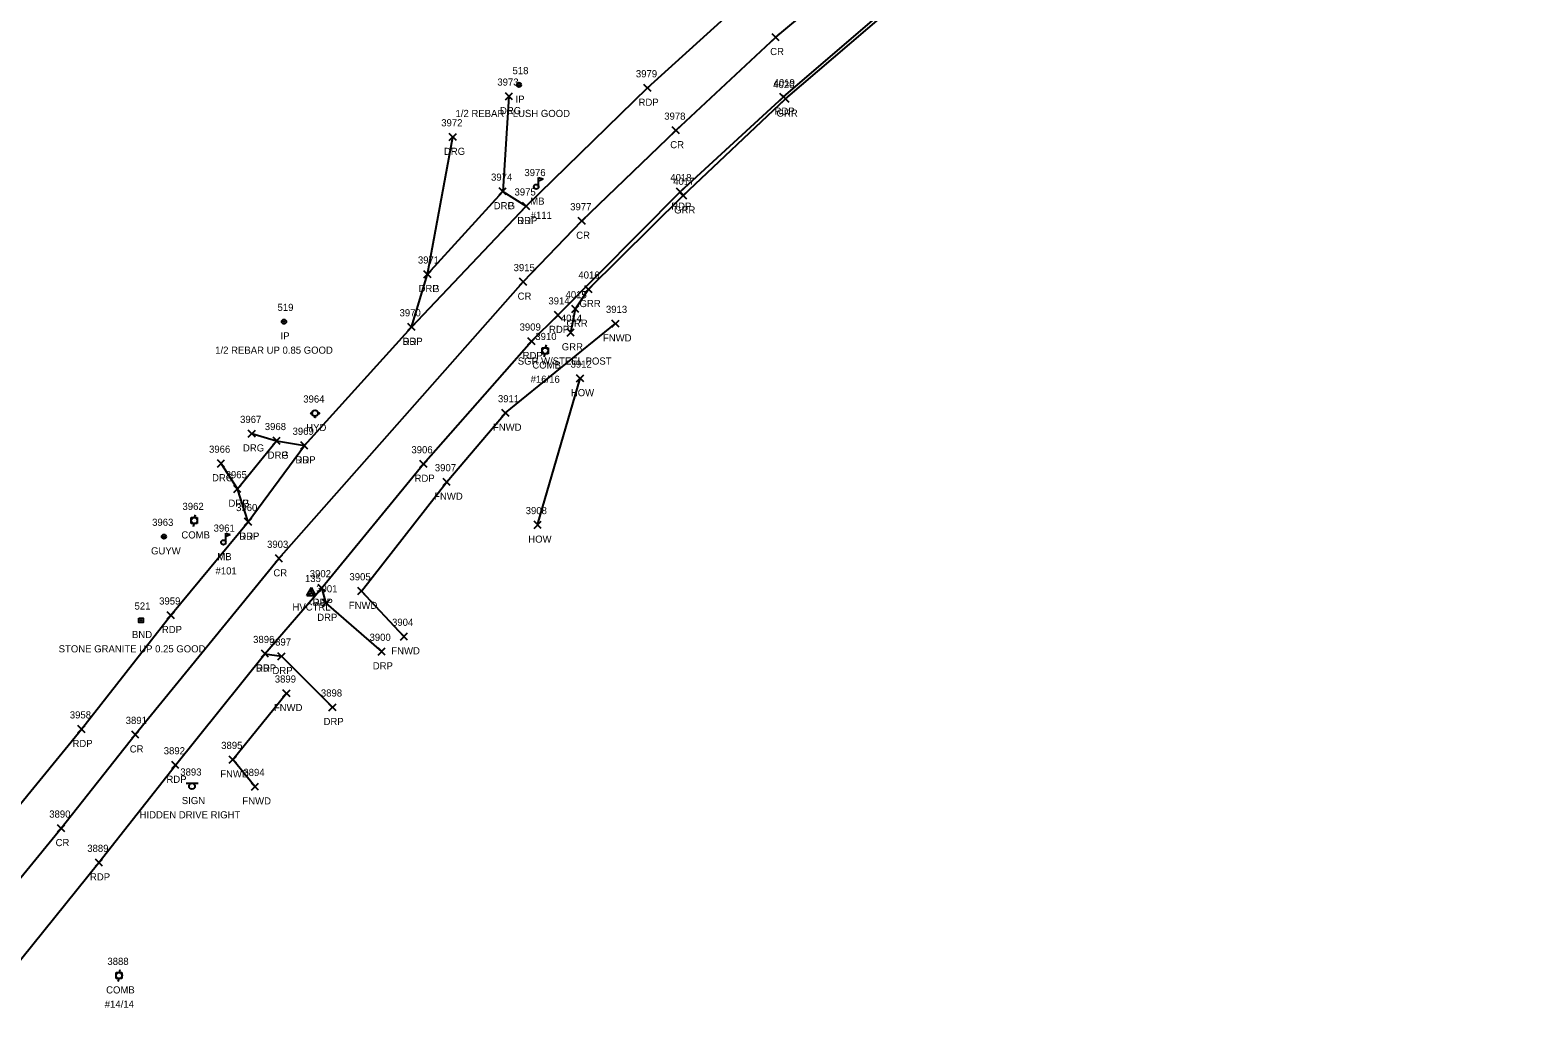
# Model space of a CAD drawing. Extents: x 1690689 to 1696275, y 438760 to 444007.
# Drawn here: x 1692607.6 to 1693030.5, y 442902 to 443176 of the extents above; entities that cross this region are included whole.
import ezdxf

# ---------------------------------------------------------------- set-up
doc = ezdxf.new("R2010")
doc.units = 0
for name, color, linetype in [('C_A', 7, 'Continuous'), ('C_I', 7, 'Continuous'), ('CPSM', 7, 'Continuous'), ('L_A', 7, 'Continuous'), ('L_C', 7, 'Continuous'), ('L_I', 7, 'Continuous'), ('L_TIC', 7, 'Continuous'), ('LBC', 7, 'Continuous'), ('Level 18', 7, 'Continuous'), ('LFNC', 7, 'Continuous'), ('LMB', 7, 'Continuous'), ('M_A', 7, 'Continuous'), ('M_C', 7, 'Continuous'), ('M_I', 7, 'Continuous'), ('MPIR', 7, 'Continuous'), ('P_A', 7, 'Continuous'), ('P_I', 7, 'Continuous'), ('P_TIC', 7, 'Continuous'), ('PET', 7, 'Continuous'), ('PRC', 7, 'Continuous'), ('R_A', 7, 'Continuous'), ('R_C', 7, 'Continuous'), ('R_I', 7, 'Continuous'), ('R_TIC', 7, 'Continuous'), ('RDG', 7, 'Continuous'), ('RDP', 7, 'Continuous'), ('RGR', 7, 'Continuous'), ('S_A', 7, 'Continuous'), ('S_C', 7, 'Continuous'), ('S_I', 7, 'Continuous'), ('SSGN', 7, 'Continuous'), ('U_A', 7, 'Continuous'), ('U_C', 7, 'Continuous'), ('U_I', 7, 'Continuous'), ('UP', 7, 'Continuous'), ('UPGW', 7, 'Continuous'), ('UWFH', 7, 'Continuous')]:
    doc.layers.add(name, color=color, linetype=linetype)

msp = doc.modelspace()

# ---------------------------------------------------------------- linework, layer by layer
at = {"layer": 'CPSM'}
for p, q in [((1692685.27, 443017.61), (1692686.52, 443019.78)), ((1692685.27, 443017.61), (1692686.52, 443018.34)), ((1692685.27, 443017.61), (1692687.77, 443017.61)), ((1692687.77, 443017.61), (1692686.52, 443019.78)), ((1692686.52, 443018.34), (1692686.52, 443019.78)), ((1692686.52, 443018.34), (1692686.52, 443018.34)), ((1692686.52, 443018.34), (1692687.77, 443017.61))]:
    msp.add_line(p, q, dxfattribs=at)
at = {"layer": 'L_TIC'}
for points in [[(1692770.81, 443092.78), (1692772.81, 443094.78)], [(1692772.81, 443092.78), (1692770.81, 443094.78)], [(1692760.89, 443077.43), (1692762.89, 443079.43)], [(1692762.89, 443077.43), (1692760.89, 443079.43)], [(1692739.97, 443067.73), (1692741.97, 443069.73)], [(1692741.97, 443067.73), (1692739.97, 443069.73)], [(1692723.48, 443048.39), (1692725.48, 443050.39)], [(1692725.48, 443048.39), (1692723.48, 443050.39)], [(1692748.95, 443036.37), (1692750.95, 443038.37)], [(1692750.95, 443036.37), (1692748.95, 443038.37)], [(1692699.53, 443017.82), (1692701.53, 443019.82)], [(1692701.53, 443017.82), (1692699.53, 443019.82)], [(1692711.47, 443005.06), (1692713.47, 443007.06)], [(1692713.47, 443005.06), (1692711.47, 443007.06)], [(1692678.52, 442989.16), (1692680.52, 442991.16)], [(1692680.52, 442989.16), (1692678.52, 442991.16)], [(1692663.48, 442970.55), (1692665.48, 442972.55)], [(1692665.48, 442970.55), (1692663.48, 442972.55)], [(1692669.7, 442962.98), (1692671.7, 442964.98)], [(1692671.7, 442962.98), (1692669.7, 442964.98)]]:
    msp.add_lwpolyline(points, dxfattribs=at)
at = {"layer": 'LBC'}
msp.add_lwpolyline([(1692749.95, 443037.37), (1692761.89, 443078.43)], dxfattribs=at)
at = {"layer": 'Level 18'}
msp.add_lwpolyline([(1692638.09, 443011.24), (1692639.34, 443011.24), (1692639.34, 443009.99), (1692638.09, 443009.99)], close=True, dxfattribs=at)
msp.add_circle((1692638.72, 443010.62), 0.0833, dxfattribs=at)
at = {"layer": 'LFNC'}
for points in [[(1692712.47, 443006.06), (1692700.53, 443018.82), (1692724.48, 443049.39), (1692740.97, 443068.73), (1692771.81, 443093.78)], [(1692670.7, 442963.98), (1692664.48, 442971.55), (1692679.52, 442990.16)]]:
    msp.add_lwpolyline(points, dxfattribs=at)
at = {"layer": 'LMB'}
for p, q in [((1692750.22, 443134.73), (1692751.51, 443134.35)), ((1692750.22, 443132.14), (1692750.22, 443134.73)), ((1692749.57, 443132.13), (1692749.57, 443132.13)), ((1692750.22, 443133.83), (1692751.51, 443134.34)), ((1692662.48, 443035.06), (1692663.78, 443034.68)), ((1692662.49, 443032.47), (1692662.49, 443035.06)), ((1692662.49, 443034.16), (1692663.77, 443034.67)), ((1692661.83, 443032.46), (1692661.83, 443032.46))]:
    msp.add_line(p, q, dxfattribs=at)
for centre in [(1692749.57, 443132.13), (1692661.83, 443032.46)]:
    msp.add_circle(centre, 0.656, dxfattribs=at)
at = {"layer": 'MPIR'}
for centre, radius in [((1692744.72, 443160.7), 0.625), ((1692744.72, 443160.7), 0.0833), ((1692678.82, 443094.34), 0.625), ((1692678.82, 443094.34), 0.0833)]:
    msp.add_circle(centre, radius, dxfattribs=at)
at = {"layer": 'P_TIC'}
for points in [[(1692815.74, 443173.05), (1692817.74, 443175.05)], [(1692817.74, 443173.05), (1692815.74, 443175.05)], [(1692779.79, 443158.83), (1692781.79, 443160.83)], [(1692781.79, 443158.83), (1692779.79, 443160.83)], [(1692817.93, 443156.32), (1692819.93, 443158.32)], [(1692819.93, 443156.32), (1692817.93, 443158.32)], [(1692787.73, 443146.94), (1692789.73, 443148.94)], [(1692789.73, 443146.94), (1692787.73, 443148.94)], [(1692788.94, 443129.71), (1692790.94, 443131.71)], [(1692790.94, 443129.71), (1692788.94, 443131.71)], [(1692745.74, 443125.69), (1692747.74, 443127.69)], [(1692747.74, 443125.69), (1692745.74, 443127.69)], [(1692761.35, 443121.55), (1692763.35, 443123.55)], [(1692763.35, 443121.55), (1692761.35, 443123.55)], [(1692744.92, 443104.48), (1692746.92, 443106.48)], [(1692746.92, 443104.48), (1692744.92, 443106.48)], [(1692754.67, 443095.16), (1692756.67, 443097.16)], [(1692756.67, 443095.16), (1692754.67, 443097.16)], [(1692713.59, 443091.82), (1692715.59, 443093.82)], [(1692715.59, 443091.82), (1692713.59, 443093.82)], [(1692747.26, 443087.83), (1692749.26, 443089.83)], [(1692749.26, 443087.83), (1692747.26, 443089.83)], [(1692683.56, 443058.61), (1692685.56, 443060.61)], [(1692685.56, 443058.61), (1692683.56, 443060.61)], [(1692716.97, 443053.43), (1692718.97, 443055.43)], [(1692718.97, 443053.43), (1692716.97, 443055.43)], [(1692667.8, 443037.22), (1692669.8, 443039.22)], [(1692669.8, 443037.22), (1692667.8, 443039.22)], [(1692676.42, 443026.92), (1692678.42, 443028.92)], [(1692678.42, 443026.92), (1692676.42, 443028.92)], [(1692688.4, 443018.68), (1692690.4, 443020.68)], [(1692690.4, 443018.68), (1692688.4, 443020.68)], [(1692646.09, 443011.03), (1692648.09, 443013.03)], [(1692648.09, 443011.03), (1692646.09, 443013.03)], [(1692672.5, 443000.25), (1692674.5, 443002.25)], [(1692674.5, 443000.25), (1692672.5, 443002.25)], [(1692621.03, 442979.1), (1692623.03, 442981.1)], [(1692623.03, 442979.1), (1692621.03, 442981.1)], [(1692636.13, 442977.56), (1692638.13, 442979.56)], [(1692638.13, 442977.56), (1692636.13, 442979.56)], [(1692647.37, 442969.05), (1692649.37, 442971.05)], [(1692649.37, 442969.05), (1692647.37, 442971.05)], [(1692615.35, 442951.3), (1692617.35, 442953.3)], [(1692617.35, 442951.3), (1692615.35, 442953.3)], [(1692625.93, 442941.69), (1692627.93, 442943.69)], [(1692627.93, 442941.69), (1692625.93, 442943.69)]]:
    msp.add_lwpolyline(points, dxfattribs=at)
at = {"layer": 'PET'}
for points in [[(1692591.46, 442942.81), (1692622.03, 442980.1), (1692647.09, 443012.03), (1692668.8, 443038.22), (1692684.56, 443059.61), (1692714.59, 443092.82), (1692746.74, 443126.69), (1692780.79, 443159.83), (1692807.32, 443183.9), (1692839.3, 443210.33), (1692872.53, 443236.3), (1692903.13, 443258.17), (1692939.2, 443281.54), (1692974.75, 443302.87), (1692999.86, 443315.16), (1693039.51, 443332.73)], [(1692595.99, 442904.43), (1692626.93, 442942.69), (1692648.37, 442970.05), (1692673.5, 443001.25), (1692689.4, 443019.68), (1692717.97, 443054.43), (1692748.26, 443088.83), (1692755.67, 443096.16), (1692789.94, 443130.71), (1692818.93, 443157.32), (1692855.61, 443188.95), (1692879.42, 443207.12), (1692910.49, 443229.68), (1692948.81, 443254.61), (1692973.05, 443269.42), (1692989.93, 443278.71), (1693016.04, 443291.45), (1693050.1, 443306.8)]]:
    msp.add_lwpolyline(points, dxfattribs=at)
at = {"layer": 'PRC'}
msp.add_lwpolyline([(1692583.2, 442911.84), (1692616.35, 442952.3), (1692637.13, 442978.56), (1692677.42, 443027.92), (1692745.92, 443105.48), (1692762.35, 443122.55), (1692788.73, 443147.94), (1692816.74, 443174.05), (1692846.74, 443199.1), (1692880.07, 443224.67), (1692910.65, 443246.02), (1692944.91, 443268.13), (1692980.95, 443289.43), (1693006.77, 443302.6), (1693041.47, 443318.25), (1693085.17, 443334.93), (1693121.18, 443346.84), (1693162.32, 443358.82), (1693209.52, 443371.25), (1693338.17, 443402.8), (1693400.05, 443418.88), (1693519.35, 443451.5)], dxfattribs=at)
at = {"layer": 'R_TIC'}
for points in [[(1692740.93, 443156.49), (1692742.93, 443158.49)], [(1692742.93, 443156.49), (1692740.93, 443158.49)], [(1692818.47, 443155.79), (1692820.47, 443157.79)], [(1692820.47, 443155.79), (1692818.47, 443157.79)], [(1692725.19, 443145.08), (1692727.19, 443147.08)], [(1692727.19, 443145.08), (1692725.19, 443147.08)], [(1692739.16, 443129.84), (1692741.16, 443131.84)], [(1692741.16, 443129.84), (1692739.16, 443131.84)], [(1692739.16, 443129.84), (1692741.16, 443131.84)], [(1692741.16, 443129.84), (1692739.16, 443131.84)], [(1692789.76, 443128.65), (1692791.76, 443130.65)], [(1692791.76, 443128.65), (1692789.76, 443130.65)], [(1692745.74, 443125.69), (1692747.74, 443127.69)], [(1692747.74, 443125.69), (1692745.74, 443127.69)], [(1692718.08, 443106.62), (1692720.08, 443108.62)], [(1692720.08, 443106.62), (1692718.08, 443108.62)], [(1692718.08, 443106.62), (1692720.08, 443108.62)], [(1692720.08, 443106.62), (1692718.08, 443108.62)], [(1692763.22, 443102.41), (1692765.22, 443104.41)], [(1692765.22, 443102.41), (1692763.22, 443104.41)], [(1692759.56, 443096.9), (1692761.56, 443098.9)], [(1692761.56, 443096.9), (1692759.56, 443098.9)], [(1692713.59, 443091.82), (1692715.59, 443093.82)], [(1692715.59, 443091.82), (1692713.59, 443093.82)], [(1692758.25, 443090.29), (1692760.25, 443092.29)], [(1692760.25, 443090.29), (1692758.25, 443092.29)], [(1692668.83, 443061.94), (1692670.83, 443063.94)], [(1692670.83, 443061.94), (1692668.83, 443063.94)], [(1692675.76, 443059.93), (1692677.76, 443061.93)], [(1692677.76, 443059.93), (1692675.76, 443061.93)], [(1692675.76, 443059.93), (1692677.76, 443061.93)], [(1692677.76, 443059.93), (1692675.76, 443061.93)], [(1692683.56, 443058.61), (1692685.56, 443060.61)], [(1692685.56, 443058.61), (1692683.56, 443060.61)], [(1692660.17, 443053.58), (1692662.17, 443055.58)], [(1692662.17, 443053.58), (1692660.17, 443055.58)], [(1692664.77, 443046.44), (1692666.77, 443048.44)], [(1692666.77, 443046.44), (1692664.77, 443048.44)], [(1692664.77, 443046.44), (1692666.77, 443048.44)], [(1692666.77, 443046.44), (1692664.77, 443048.44)], [(1692667.8, 443037.22), (1692669.8, 443039.22)], [(1692669.8, 443037.22), (1692667.8, 443039.22)], [(1692688.4, 443018.68), (1692690.4, 443020.68)], [(1692690.4, 443018.68), (1692688.4, 443020.68)], [(1692689.65, 443014.46), (1692691.65, 443016.46)], [(1692691.65, 443014.46), (1692689.65, 443016.46)], [(1692672.5, 443000.25), (1692674.5, 443002.25)], [(1692674.5, 443000.25), (1692672.5, 443002.25)], [(1692677.12, 442999.53), (1692679.12, 443001.53)], [(1692679.12, 442999.53), (1692677.12, 443001.53)], [(1692705.25, 443000.85), (1692707.25, 443002.85)], [(1692707.25, 443000.85), (1692705.25, 443002.85)], [(1692691.44, 442985.24), (1692693.44, 442987.24)], [(1692693.44, 442985.24), (1692691.44, 442987.24)]]:
    msp.add_lwpolyline(points, dxfattribs=at)
at = {"layer": 'RDG'}
for points in [[(1692741.93, 443157.49), (1692740.16, 443130.84)], [(1692719.08, 443107.62), (1692726.19, 443146.08)], [(1692669.83, 443062.94), (1692676.76, 443060.93)], [(1692665.77, 443047.44), (1692661.17, 443054.58)]]:
    msp.add_lwpolyline(points, dxfattribs=at)
at = {"layer": 'RDP'}
for points in [[(1692714.59, 443092.82), (1692719.08, 443107.62), (1692740.16, 443130.84), (1692746.74, 443126.69)], [(1692668.8, 443038.22), (1692665.77, 443047.44), (1692676.76, 443060.93), (1692684.56, 443059.61)], [(1692706.25, 443001.85), (1692690.65, 443015.46), (1692689.4, 443019.68)], [(1692673.5, 443001.25), (1692678.12, 443000.53), (1692692.44, 442986.24)]]:
    msp.add_lwpolyline(points, dxfattribs=at)
at = {"layer": 'RGR'}
msp.add_lwpolyline([(1692759.25, 443091.29), (1692760.56, 443097.9), (1692764.22, 443103.41), (1692790.76, 443129.65), (1692819.47, 443156.79), (1692856.05, 443188.06), (1692879.74, 443206.5), (1692910.87, 443228.78), (1692949.22, 443253.64), (1692955.52, 443255.12), (1692961.03, 443254.4)], dxfattribs=at)
at = {"layer": 'SSGN'}
for p, q in [((1692651.38, 442964.94), (1692654.72, 442964.94)), ((1692653.03, 442964.11), (1692653.03, 442964.11))]:
    msp.add_line(p, q, dxfattribs=at)
msp.add_circle((1692653.03, 442964.11), 0.833, dxfattribs=at)
at = {"layer": 'UP'}
for p, q in [((1692751.26, 443085.34), (1692751.26, 443087.01)), ((1692751.26, 443087.01), (1692752.93, 443087.01)), ((1692752.93, 443085.34), (1692751.26, 443085.34)), ((1692751.84, 443084.51), (1692752.09, 443085.34)), ((1692752.34, 443087.84), (1692752.09, 443087.01)), ((1692752.09, 443086.18), (1692752.09, 443086.18)), ((1692752.93, 443087.01), (1692752.93, 443085.34)), ((1692652.83, 443037.72), (1692652.83, 443039.39)), ((1692652.83, 443039.39), (1692654.5, 443039.39)), ((1692654.5, 443037.72), (1692652.83, 443037.72)), ((1692653.42, 443036.89), (1692653.67, 443037.72)), ((1692653.92, 443040.22), (1692653.67, 443039.39)), ((1692653.67, 443038.55), (1692653.67, 443038.55)), ((1692654.5, 443039.39), (1692654.5, 443037.72)), ((1692631.74, 442910.17), (1692631.74, 442911.84)), ((1692631.74, 442911.84), (1692633.4, 442911.84)), ((1692632.82, 442912.67), (1692632.57, 442911.84)), ((1692632.57, 442911.01), (1692632.57, 442911.01)), ((1692633.4, 442911.84), (1692633.4, 442910.17)), ((1692633.4, 442910.17), (1692631.74, 442910.17)), ((1692632.32, 442909.34), (1692632.57, 442910.17))]:
    msp.add_line(p, q, dxfattribs=at)
for centre in [(1692752.09, 443086.18), (1692653.67, 443038.55), (1692632.57, 442911.01)]:
    msp.add_circle(centre, 0.833, dxfattribs=at)
at = {"layer": 'UPGW'}
for radius in [0.625, 0.0833]:
    msp.add_circle((1692645.16, 443034.08), radius, dxfattribs=at)
at = {"layer": 'UWFH'}
msp.add_line((1692687.55, 443068.65), (1692687.55, 443068.65), dxfattribs=at)
for centre, radius in [((1692686.55, 443068.65), 0.167), ((1692687.55, 443068.65), 0.833), ((1692687.55, 443067.65), 0.167), ((1692688.55, 443068.65), 0.167)]:
    msp.add_circle(centre, radius, dxfattribs=at)

# ---------------------------------------------------------------- texts
at = {"layer": 'C_A'}
msp.add_text('HVCTRL', height=2, dxfattribs=at).set_placement((1692681.21, 443013.34))
at = {"layer": 'C_I'}
msp.add_text('135', height=2, dxfattribs=at).set_placement((1692684.72, 443021.34))
at = {"layer": 'L_A'}
for s, p in [('MB', (1692747.88, 443127.13)), ('FNWD', (1692768.28, 443088.78)), ('HOW', (1692759.28, 443073.43)), ('FNWD', (1692737.43, 443063.73)), ('FNWD', (1692720.94, 443044.39)), ('HOW', (1692747.34, 443032.37)), ('MB', (1692660.14, 443027.46)), ('FNWD', (1692697, 443013.82)), ('FNWD', (1692708.93, 443001.06)), ('FNWD', (1692675.99, 442985.16)), ('FNWD', (1692660.95, 442966.55)), ('FNWD', (1692667.16, 442958.98))]:
    msp.add_text(s, height=2, dxfattribs=at).set_placement(p)
at = {"layer": 'L_C'}
for s, p in [('#111', (1692748.01, 443123.13)), ('#101', (1692659.63, 443023.46))]:
    msp.add_text(s, height=2, dxfattribs=at).set_placement(p)
at = {"layer": 'L_I'}
for s, p in [('3976', (1692746.25, 443135.13)), ('3913', (1692769.12, 443096.78)), ('3912', (1692759.2, 443081.43)), ('3911', (1692738.84, 443071.73)), ('3907', (1692721.14, 443052.39)), ('3908', (1692746.61, 443040.37)), ('3961', (1692659.09, 443035.46)), ('3905', (1692697.19, 443021.82)), ('3904', (1692709.13, 443009.06)), ('3899', (1692676.25, 442993.16)), ('3895', (1692661.22, 442974.55)), ('3894', (1692667.44, 442966.98))]:
    msp.add_text(s, height=2, dxfattribs=at).set_placement(p)
at = {"layer": 'M_A'}
for s, p in [('IP', (1692743.76, 443155.7)), ('IP', (1692677.87, 443089.34)), ('BND', (1692636.2, 443005.62))]:
    msp.add_text(s, height=2, dxfattribs=at).set_placement(p)
at = {"layer": 'M_C'}
for s, p in [('1/2 REBAR FLUSH GOOD', (1692726.94, 443151.7)), ('1/2 REBAR UP 0.85 GOOD', (1692659.54, 443085.34)), ('STONE GRANITE UP 0.25 GOOD', (1692615.64, 443001.62))]:
    msp.add_text(s, height=2, dxfattribs=at).set_placement(p)
at = {"layer": 'M_I'}
for s, p in [('518', (1692742.92, 443163.7)), ('519', (1692677.02, 443097.34)), ('521', (1692636.92, 443013.62))]:
    msp.add_text(s, height=2, dxfattribs=at).set_placement(p)
at = {"layer": 'P_A'}
for s, p in [('CR', (1692815.18, 443169.05)), ('RDP', (1692778.27, 443154.83)), ('RDP', (1692816.42, 443152.32)), ('CR', (1692787.16, 443142.94)), ('RDP', (1692787.43, 443125.71)), ('RDP', (1692744.23, 443121.69)), ('CR', (1692760.78, 443117.55)), ('CR', (1692744.35, 443100.48)), ('RDP', (1692753.16, 443091.16)), ('RDP', (1692712.08, 443087.82)), ('RDP', (1692745.75, 443083.83)), ('RDP', (1692682.04, 443054.61)), ('RDP', (1692715.45, 443049.43)), ('RDP', (1692666.28, 443033.22)), ('CR', (1692675.86, 443022.92)), ('RDP', (1692686.88, 443014.68)), ('RDP', (1692644.58, 443007.03)), ('RDP', (1692670.98, 442996.25)), ('RDP', (1692619.52, 442975.1)), ('CR', (1692635.57, 442973.56)), ('RDP', (1692645.86, 442965.05)), ('CR', (1692614.78, 442947.3)), ('RDP', (1692624.42, 442937.69))]:
    msp.add_text(s, height=2, dxfattribs=at).set_placement(p)
at = {"layer": 'P_I'}
for s, p in [('3979', (1692777.52, 443162.83)), ('4019', (1692816.15, 443160.32)), ('3978', (1692785.47, 443150.94)), ('4018', (1692787.17, 443133.71)), ('3975', (1692743.48, 443129.69)), ('3977', (1692759.09, 443125.55)), ('3915', (1692743.23, 443108.48)), ('3914', (1692752.98, 443099.16)), ('3970', (1692711.24, 443095.82)), ('3909', (1692744.91, 443091.83)), ('3969', (1692681.24, 443062.61)), ('3906', (1692714.57, 443057.43)), ('3960', (1692665.4, 443041.22)), ('3903', (1692674.08, 443030.92)), ('3902', (1692686.06, 443022.68)), ('3959', (1692643.82, 443015.03)), ('3896', (1692670.18, 443004.25)), ('3958', (1692618.77, 442983.1)), ('3891', (1692634.44, 442981.56)), ('3892', (1692645.11, 442973.05)), ('3890', (1692613, 442955.3)), ('3889', (1692623.66, 442945.69))]:
    msp.add_text(s, height=2, dxfattribs=at).set_placement(p)
at = {"layer": 'R_A'}
for s, p in [('DRG', (1692739.41, 443152.49)), ('GRR', (1692816.96, 443151.79)), ('DRG', (1692723.68, 443141.08)), ('DRG', (1692737.65, 443125.84)), ('DRP', (1692737.65, 443125.84)), ('GRR', (1692788.25, 443124.65)), ('DRP', (1692744.23, 443121.69)), ('DRG', (1692716.57, 443102.62)), ('DRP', (1692716.57, 443102.62)), ('GRR', (1692761.71, 443098.41)), ('GRR', (1692758.05, 443092.9)), ('DRP', (1692712.08, 443087.82)), ('GRR', (1692756.73, 443086.29)), ('DRG', (1692667.32, 443057.94)), ('DRG', (1692674.25, 443055.93)), ('DRP', (1692674.25, 443055.93)), ('DRP', (1692682.04, 443054.61)), ('DRG', (1692658.66, 443049.58)), ('DRG', (1692663.26, 443042.44)), ('DRP', (1692663.26, 443042.44)), ('DRP', (1692666.28, 443033.22)), ('DRP', (1692686.88, 443014.68)), ('DRP', (1692688.14, 443010.46)), ('DRP', (1692670.98, 442996.25)), ('DRP', (1692675.6, 442995.53)), ('DRP', (1692703.73, 442996.85)), ('DRP', (1692689.93, 442981.24))]:
    msp.add_text(s, height=2, dxfattribs=at).set_placement(p)
at = {"layer": 'R_C'}
msp.add_text('SGR W/STEEL POST', height=2, dxfattribs=at).set_placement((1692744.39, 443082.29))
at = {"layer": 'R_I'}
for s, p in [('3973', (1692738.67, 443160.49)), ('4020', (1692816.04, 443159.79)), ('3972', (1692722.93, 443149.08)), ('3974', (1692736.9, 443133.84)), ('3974', (1692736.9, 443133.84)), ('4017', (1692787.99, 443132.65)), ('3975', (1692743.48, 443129.69)), ('3971', (1692716.39, 443110.62)), ('3971', (1692716.39, 443110.62)), ('4016', (1692761.39, 443106.41)), ('4015', (1692757.79, 443100.9)), ('3970', (1692711.24, 443095.82)), ('4014', (1692756.47, 443094.29)), ('3967', (1692666.52, 443065.94)), ('3968', (1692673.45, 443063.93)), ('3968', (1692673.45, 443063.93)), ('3969', (1692681.24, 443062.61)), ('3966', (1692657.81, 443057.58)), ('3965', (1692662.47, 443050.44)), ('3965', (1692662.47, 443050.44)), ('3960', (1692665.4, 443041.22)), ('3902', (1692686.06, 443022.68)), ('3901', (1692687.88, 443018.46)), ('3896', (1692670.18, 443004.25)), ('3897', (1692674.86, 443003.53)), ('3900', (1692702.82, 443004.85)), ('3898', (1692689.18, 442989.24))]:
    msp.add_text(s, height=2, dxfattribs=at).set_placement(p)
at = {"layer": 'S_A'}
msp.add_text('SIGN', height=2, dxfattribs=at).set_placement((1692650.17, 442959.09))
at = {"layer": 'S_C'}
msp.add_text('HIDDEN DRIVE RIGHT', height=2, dxfattribs=at).set_placement((1692638.34, 442955.09))
at = {"layer": 'S_I'}
msp.add_text('3893', height=2, dxfattribs=at).set_placement((1692649.75, 442967.09))
at = {"layer": 'U_A'}
for s, p in [('COMB', (1692748.48, 443081.18)), ('HYD', (1692685.07, 443063.65)), ('COMB', (1692650.05, 443033.55)), ('GUYW', (1692641.55, 443029.08)), ('COMB', (1692628.95, 442906.01))]:
    msp.add_text(s, height=2, dxfattribs=at).set_placement(p)
at = {"layer": 'U_C'}
for s, p in [('#16/16', (1692747.99, 443077.18)), ('#14/14', (1692628.57, 442902.01))]:
    msp.add_text(s, height=2, dxfattribs=at).set_placement(p)
at = {"layer": 'U_I'}
for s, p in [('3910', (1692749.32, 443089.18)), ('3964', (1692684.24, 443071.65)), ('3962', (1692650.36, 443041.55)), ('3963', (1692641.85, 443037.08)), ('3888', (1692629.31, 442914.01))]:
    msp.add_text(s, height=2, dxfattribs=at).set_placement(p)

doc.saveas('drawing.dxf')
